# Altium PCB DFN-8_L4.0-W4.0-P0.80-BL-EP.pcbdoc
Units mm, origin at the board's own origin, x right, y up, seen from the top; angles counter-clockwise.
Board outline 16.85 x 18.1 mm, 2 copper layers (Top Layer, Bottom Layer), stack 0 mm thick; 1 components, 0 nets, 9 pads, 0 vias.
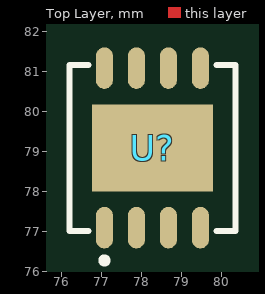
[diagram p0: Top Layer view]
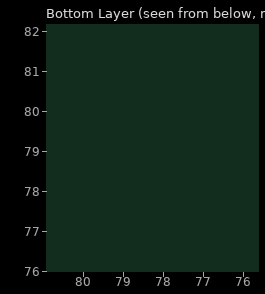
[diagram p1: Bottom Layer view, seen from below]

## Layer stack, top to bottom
Top Layer: signal copper (thickness not stored)
Bottom Layer: signal copper (thickness not stored)

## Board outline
86.702,69.85 69.85,69.85 69.85,87.953 86.702,87.953

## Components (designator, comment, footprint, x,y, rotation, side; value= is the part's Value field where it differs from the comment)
U? "" DFN-8_L4.0-W4.0-P0.80-BL-EP 78.276,79.09 r0 top

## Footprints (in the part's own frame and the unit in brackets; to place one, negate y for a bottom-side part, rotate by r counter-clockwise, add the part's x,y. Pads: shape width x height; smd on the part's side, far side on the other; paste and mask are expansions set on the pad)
DFN-8_L4.0-W4.0-P0.80-BL-EP [mm]
  oval 0.427x1.039 smd: 1(-1.2,-1.994) 2(-0.4,-1.994) 3(0.4,-1.994) 4(1.2,-1.994) 5(1.2,1.994) 6(0.4,1.994) 7(-0.4,1.994) 8(-1.2,1.994)
  rect 3.025x2.175 smd: 9(0,0)
  silkscreen extent -2.08,-2.89 2.08,2.08

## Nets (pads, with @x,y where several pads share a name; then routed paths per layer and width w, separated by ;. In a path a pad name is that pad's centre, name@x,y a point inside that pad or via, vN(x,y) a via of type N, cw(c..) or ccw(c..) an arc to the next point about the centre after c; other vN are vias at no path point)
pads on no net: U?.1 U?.2 U?.3 U?.4 U?.5 U?.6 U?.7 U?.8 U?.9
